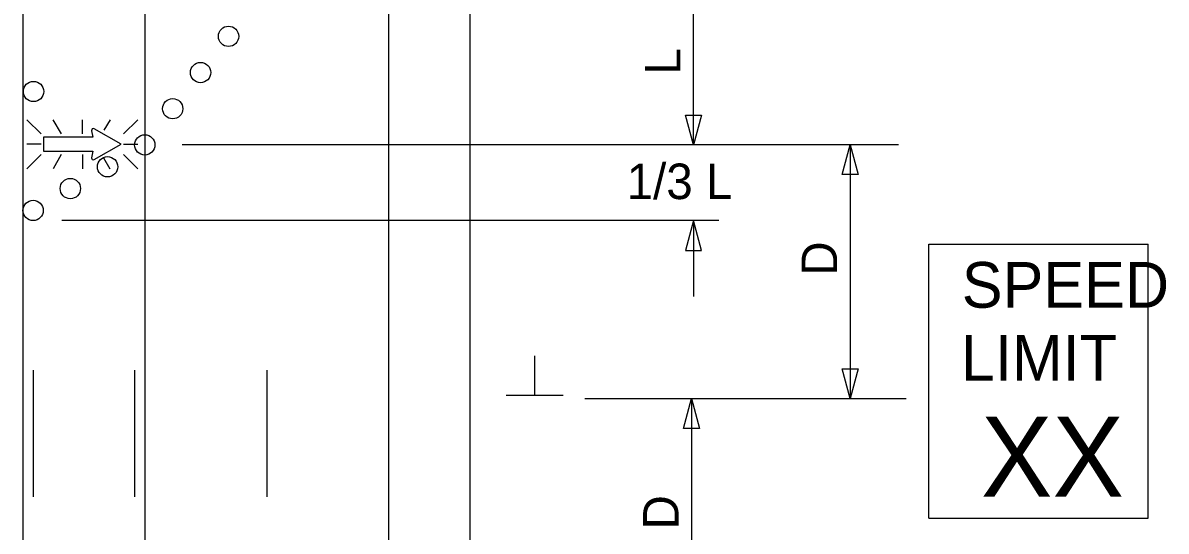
# Model space of a CAD drawing. Extents: x 16733 to 18475, y 5693 to 6915.
# Drawn here: x 17011.4 to 17236.5, y 6343.9 to 6444 of the extents above; entities that cross this region are included whole.
import ezdxf

# ---------------------------------------------------------------- set-up
doc = ezdxf.new("R2010")
doc.units = 0
for name, color, linetype in [('ALI_LEGAL_EX', 7, 'Continuous'), ('PAVT_EDGE_EX', 7, 'Continuous'), ('TRAFFIC_SIGNS_PR', 7, 'Continuous'), ('TYPICAL_TEXT_DIMEN_PR', 7, 'Continuous')]:
    doc.layers.add(name, color=color, linetype=linetype)

msp = doc.modelspace()

# ---------------------------------------------------------------- linework, layer by layer
at = {"layer": 'ALI_LEGAL_EX'}
for points in [[(17013.43, 6375.6), (17013.43, 6350.6)], [(17033.43, 6375.6), (17033.43, 6350.6)], [(17059.43, 6375.6), (17059.43, 6350.6)]]:
    msp.add_lwpolyline(points, dxfattribs=at)
at = {"layer": 'PAVT_EDGE_EX'}
for p, q in [((17011.43, 6893.09), (17011.43, 6095.81)), ((17035.43, 6893.09), (17035.43, 6095.81)), ((17083.43, 6893.09), (17083.43, 6095.81)), ((17099.43, 6893.09), (17099.43, 6095.81))]:
    msp.add_line(p, q, dxfattribs=at)
at = {"layer": 'TRAFFIC_SIGNS_PR'}
for p, q in [((17015.05, 6422.12), (17012.23, 6424.94)), ((17017.35, 6424.94), (17018.98, 6422.12)), ((17023.14, 6422.12), (17023.14, 6424.94)), ((17028.61, 6424.94), (17027.4, 6422.85)), ((17034.04, 6424.94), (17031.22, 6422.12)), ((17015.05, 6420.09), (17012.23, 6420.09)), ((17031.22, 6420.09), (17034.04, 6420.09)), ((17015.05, 6418.06), (17012.23, 6415.24)), ((17019, 6418.06), (17017.38, 6415.24)), ((17023.14, 6418.06), (17023.14, 6415.24)), ((17027.32, 6417.42), (17028.58, 6415.24)), ((17034.04, 6415.24), (17031.22, 6418.06)), ((17189.76, 6400.42), (17232.96, 6400.42)), ((17189.76, 6346.42), (17189.76, 6400.42)), ((17232.96, 6346.42), (17232.96, 6400.42)), ((17189.76, 6346.42), (17232.96, 6346.42))]:
    msp.add_line(p, q, dxfattribs=at)
for points in [[(17024.97, 6422.77), (17025.19, 6421.48), (17015.47, 6421.48), (17015.47, 6418.73), (17025.19, 6418.73), (17024.96, 6417.43)], [(17025.47, 6417.08), (17030.77, 6420.09), (17025.46, 6423.13)]]:
    msp.add_lwpolyline(points, dxfattribs=at)
for centre in [(17051.92, 6441.36), (17046.42, 6434.23), (17013.53, 6430.49), (17040.93, 6427.1), (17035.43, 6419.97), (17028.11, 6415.66), (17020.78, 6411.36), (17013.45, 6407.05)]:
    msp.add_circle(centre, 2, dxfattribs=at)
for centre, start, end in [((17025.3, 6422.83), 61.4833, 189.9593), ((17025.3, 6417.38), 170.7308, 298.8916)]:
    msp.add_arc(centre, 0.341, start, end, dxfattribs=at)
at = {"layer": 'TYPICAL_TEXT_DIMEN_PR'}
for p, q in [((17143.43, 6419.97), (17143.43, 6450.54)), ((17143.43, 6419.97), (17141.86, 6425.83)), ((17141.86, 6425.83), (17143.43, 6425.83)), ((17143.43, 6425.83), (17145, 6425.83)), ((17145, 6425.83), (17143.43, 6419.97)), ((17183.8, 6419.97), (17042.79, 6419.97)), ((17172.71, 6414.11), (17174.28, 6419.97)), ((17174.28, 6419.97), (17175.85, 6414.11)), ((17174.28, 6419.97), (17174.28, 6369.97)), ((17174.28, 6414.11), (17172.71, 6414.11)), ((17175.85, 6414.11), (17174.28, 6414.11)), ((17148.43, 6405.05), (17019.11, 6405.05)), ((17143.43, 6405.05), (17141.86, 6399.19)), ((17143.43, 6405.05), (17143.43, 6390.12)), ((17145, 6399.19), (17143.43, 6405.05)), ((17141.86, 6399.19), (17143.43, 6399.19)), ((17143.43, 6399.19), (17145, 6399.19)), ((17112.19, 6370.62), (17112.19, 6378.4)), ((17174.28, 6369.97), (17172.71, 6375.83)), ((17172.71, 6375.83), (17174.28, 6375.83)), ((17174.28, 6375.83), (17175.85, 6375.83)), ((17175.85, 6375.83), (17174.28, 6369.97)), ((17117.82, 6370.62), (17106.57, 6370.62)), ((17122.07, 6369.97), (17185.32, 6369.97)), ((17141.5, 6364.11), (17143.07, 6369.97)), ((17143.07, 6369.97), (17143.07, 6319.97)), ((17143.07, 6369.97), (17144.64, 6364.11)), ((17143.07, 6364.11), (17141.5, 6364.11)), ((17144.64, 6364.11), (17143.07, 6364.11))]:
    msp.add_line(p, q, dxfattribs=at)

# ---------------------------------------------------------------- texts
at = {"layer": 'TRAFFIC_SIGNS_PR'}
for s, height, p in [('SPEED', 9, (17196.25, 6387.89)), ('LIMIT', 9, (17196.07, 6373.49)), ('XX', 15.785, (17200.02, 6350.65))]:
    msp.add_text(s, height=height, dxfattribs=at).set_placement(p)
at = {"layer": 'TYPICAL_TEXT_DIMEN_PR'}
for s, p in [('L', (17140.88, 6433.84)), ('D', (17171.72, 6394.19)), ('D', (17140.51, 6344.19))]:
    msp.add_text(s, height=7, rotation=90, dxfattribs=at).set_placement(p)
msp.add_text('1/3 L', height=7, dxfattribs=at).set_placement((17130.28, 6409.29))

doc.saveas('drawing.dxf')
